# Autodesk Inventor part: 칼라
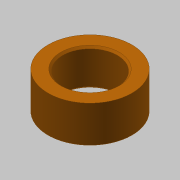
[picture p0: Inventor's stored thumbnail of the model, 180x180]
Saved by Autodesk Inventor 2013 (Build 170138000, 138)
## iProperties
Created: 2015-09
Part Number: 칼라
Document SubType Name: Modeling
Designer: mduedu
Density: 1 g/cm^3
Material: 스테인리스강
Author: mduedu
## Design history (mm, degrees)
node "작업 평면1"
node "작업 평면2"
sketch "스케치1"
  geometry: C1 r 7.5 at (0, 0); C2 r 11.5 at (0, 0); 1 further point
  constraints: 2 centre point, 2 coincident
  dimensions: "d0" = 15 diameter of C1; "d1" = 23 diameter of C2
extrude "돌출1" new body sketch "스케치1" stored distance "d2" = 9.85; taper "d3" = 0 deg
chamfer "모따기1" distance "d4" = 0.5; stored, may be unused: second distance "d5" = 2, angle "d6" = 45 deg
node "솔리드1"
